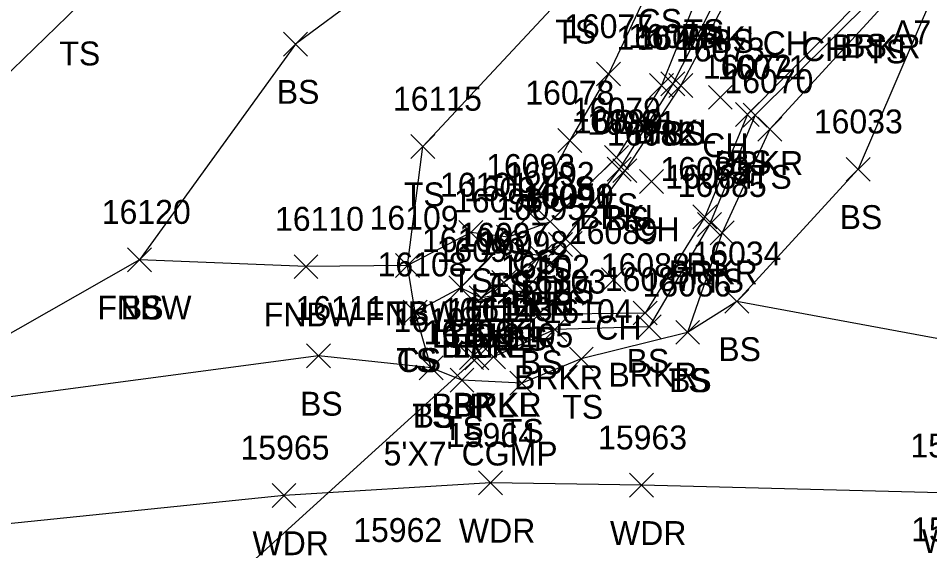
# Model space of a CAD drawing. Extents: x 1606530 to 1613020, y 784959 to 789666.
# Drawn here: x 1609253.6 to 1609329.8, y 788467.6 to 788511.7 of the extents above; entities that cross this region are included whole.
import ezdxf

# ---------------------------------------------------------------- set-up
doc = ezdxf.new("R2010")
doc.units = 0
for name, color, linetype in [('D_A', 7, 'Continuous'), ('D_C', 7, 'Continuous'), ('D_I', 7, 'Continuous'), ('D_TIC', 7, 'Continuous'), ('DCP', 7, 'Continuous'), ('L_A', 7, 'Continuous'), ('L_C', 7, 'Continuous'), ('L_I', 7, 'Continuous'), ('L_TIC', 7, 'Continuous'), ('LARO', 7, 'Continuous'), ('LAWA', 7, 'Continuous'), ('LAWE', 7, 'Continuous'), ('LELB', 7, 'Continuous'), ('LFNC', 7, 'Continuous')]:
    doc.layers.add(name, color=color, linetype=linetype)

msp = doc.modelspace()

# ---------------------------------------------------------------- linework, layer by layer
at = {"layer": 'D_TIC'}
for points in [[(1609290.934, 788482.273), (1609292.934, 788484.273)], [(1609292.934, 788482.273), (1609290.934, 788484.273)]]:
    msp.add_lwpolyline(points, dxfattribs=at)
at = {"layer": 'DCP'}
msp.add_lwpolyline([(1609180.836, 788382.354), (1609291.934, 788483.273)], dxfattribs=at)
at = {"layer": 'L_TIC'}
for points in [[(1609275.762, 788508.528), (1609277.762, 788510.528)], [(1609277.762, 788508.528), (1609275.762, 788510.528)], [(1609301.939, 788506.019), (1609303.939, 788508.019)], [(1609303.939, 788506.019), (1609301.939, 788508.019)], [(1609306.366, 788505.057), (1609308.366, 788507.057)], [(1609308.366, 788505.057), (1609306.366, 788507.057)], [(1609307.3, 788505.198), (1609309.3, 788507.198)], [(1609309.3, 788505.198), (1609307.3, 788507.198)], [(1609307.988, 788505.06), (1609309.988, 788507.06)], [(1609309.988, 788505.06), (1609307.988, 788507.06)], [(1609311.28, 788504.067), (1609313.28, 788506.067)], [(1609313.28, 788504.067), (1609311.28, 788506.067)], [(1609313.539, 788502.632), (1609315.539, 788504.632)], [(1609315.539, 788502.632), (1609313.539, 788504.632)], [(1609314.185, 788502.575), (1609316.185, 788504.575)], [(1609316.185, 788502.575), (1609314.185, 788504.575)], [(1609315.424, 788501.417), (1609317.424, 788503.417)], [(1609317.424, 788501.417), (1609315.424, 788503.417)], [(1609298.697, 788500.458), (1609300.697, 788502.458)], [(1609300.697, 788500.458), (1609298.697, 788502.458)], [(1609286.418, 788499.952), (1609288.418, 788501.952)], [(1609288.418, 788499.952), (1609286.418, 788501.952)], [(1609302.599, 788499.047), (1609304.599, 788501.047)], [(1609304.599, 788499.047), (1609302.599, 788501.047)], [(1609302.822, 788498.065), (1609304.822, 788500.065)], [(1609304.822, 788498.065), (1609302.822, 788500.065)], [(1609322.809, 788498.051), (1609324.809, 788500.051)], [(1609324.809, 788498.051), (1609322.809, 788500.051)], [(1609303.305, 788497.934), (1609305.305, 788499.934)], [(1609305.305, 788497.934), (1609303.305, 788499.934)], [(1609305.525, 788497.031), (1609307.525, 788499.031)], [(1609307.525, 788497.031), (1609305.525, 788499.031)], [(1609295.421, 788494.325), (1609297.421, 788496.325)], [(1609297.421, 788494.325), (1609295.421, 788496.325)], [(1609297.055, 788493.668), (1609299.055, 788495.668)], [(1609299.055, 788493.668), (1609297.055, 788495.668)], [(1609309.988, 788494.081), (1609311.988, 788496.081)], [(1609311.988, 788494.081), (1609309.988, 788496.081)], [(1609310.383, 788493.432), (1609312.383, 788495.432)], [(1609312.383, 788493.432), (1609310.383, 788495.432)], [(1609290.426, 788492.764), (1609292.426, 788494.764)], [(1609292.426, 788492.764), (1609290.426, 788494.764)], [(1609311.433, 788492.737), (1609313.433, 788494.737)], [(1609313.433, 788492.737), (1609311.433, 788494.737)], [(1609293.558, 788492.383), (1609295.558, 788494.383)], [(1609295.558, 788492.383), (1609293.558, 788494.383)], [(1609293.558, 788492.383), (1609295.558, 788494.383)], [(1609295.558, 788492.383), (1609293.558, 788494.383)], [(1609292.789, 788491.438), (1609294.789, 788493.438)], [(1609294.789, 788491.438), (1609292.789, 788493.438)], [(1609297.927, 788491.769), (1609299.927, 788493.769)], [(1609299.927, 788491.769), (1609297.927, 788493.769)], [(1609298.732, 788491.837), (1609300.732, 788493.837)], [(1609300.732, 788491.837), (1609298.732, 788493.837)], [(1609262.732, 788490.487), (1609264.732, 788492.487)], [(1609264.732, 788490.487), (1609262.732, 788492.487)], [(1609262.732, 788490.487), (1609264.732, 788492.487)], [(1609264.732, 788490.487), (1609262.732, 788492.487)], [(1609296.256, 788490.801), (1609298.256, 788492.801)], [(1609298.256, 788490.801), (1609296.256, 788492.801)], [(1609296.256, 788490.801), (1609298.256, 788492.801)], [(1609298.256, 788490.801), (1609296.256, 788492.801)], [(1609296.256, 788490.801), (1609298.256, 788492.801)], [(1609298.256, 788490.801), (1609296.256, 788492.801)], [(1609276.648, 788489.908), (1609278.648, 788491.908)], [(1609278.648, 788489.908), (1609276.648, 788491.908)], [(1609285.122, 788489.996), (1609287.122, 788491.996)], [(1609287.122, 788489.996), (1609285.122, 788491.996)], [(1609285.122, 788489.996), (1609287.122, 788491.996)], [(1609287.122, 788489.996), (1609285.122, 788491.996)], [(1609285.122, 788489.996), (1609287.122, 788491.996)], [(1609287.122, 788489.996), (1609285.122, 788491.996)], [(1609289.574, 788488.139), (1609291.574, 788490.139)], [(1609291.574, 788488.139), (1609289.574, 788490.139)], [(1609289.574, 788488.139), (1609291.574, 788490.139)], [(1609291.574, 788488.139), (1609289.574, 788490.139)], [(1609289.574, 788488.139), (1609291.574, 788490.139)], [(1609291.574, 788488.139), (1609289.574, 788490.139)], [(1609293.184, 788488.575), (1609295.184, 788490.575)], [(1609295.184, 788488.575), (1609293.184, 788490.575)], [(1609302.346, 788488.799), (1609304.346, 788490.799)], [(1609304.346, 788488.799), (1609302.346, 788490.799)], [(1609291.29, 788487.306), (1609293.29, 788489.306)], [(1609293.29, 788487.306), (1609291.29, 788489.306)], [(1609291.29, 788487.306), (1609293.29, 788489.306)], [(1609293.29, 788487.306), (1609291.29, 788489.306)], [(1609294.833, 788487.887), (1609296.833, 788489.887)], [(1609296.833, 788487.887), (1609294.833, 788489.887)], [(1609294.833, 788487.887), (1609296.833, 788489.887)], [(1609296.833, 788487.887), (1609294.833, 788489.887)], [(1609312.667, 788487.005), (1609314.667, 788489.005)], [(1609314.667, 788487.005), (1609312.667, 788489.005)], [(1609312.667, 788487.005), (1609314.667, 788489.005)], [(1609314.667, 788487.005), (1609312.667, 788489.005)], [(1609285.783, 788486.092), (1609287.783, 788488.092)], [(1609287.783, 788486.092), (1609285.783, 788488.092)], [(1609285.783, 788486.092), (1609287.783, 788488.092)], [(1609287.783, 788486.092), (1609285.783, 788488.092)], [(1609296.097, 788485.905), (1609298.097, 788487.905)], [(1609298.097, 788485.905), (1609296.097, 788487.905)], [(1609296.097, 788485.905), (1609298.097, 788487.905)], [(1609298.097, 788485.905), (1609296.097, 788487.905)], [(1609305.001, 788486.028), (1609307.001, 788488.028)], [(1609307.001, 788486.028), (1609305.001, 788488.028)], [(1609297.451, 788484.655), (1609299.451, 788486.655)], [(1609299.451, 788484.655), (1609297.451, 788486.655)], [(1609305.343, 788484.871), (1609307.343, 788486.871)], [(1609307.343, 788484.871), (1609305.343, 788486.871)], [(1609308.548, 788484.41), (1609310.548, 788486.41)], [(1609310.548, 788484.41), (1609308.548, 788486.41)], [(1609308.548, 788484.41), (1609310.548, 788486.41)], [(1609310.548, 788484.41), (1609308.548, 788486.41)], [(1609277.703, 788482.443), (1609279.703, 788484.443)], [(1609279.703, 788482.443), (1609277.703, 788484.443)], [(1609290.476, 788482.291), (1609292.476, 788484.291)], [(1609292.476, 788482.291), (1609290.476, 788484.291)], [(1609292.319, 788482.357), (1609294.319, 788484.357)], [(1609294.319, 788482.357), (1609292.319, 788484.357)], [(1609292.319, 788482.357), (1609294.319, 788484.357)], [(1609294.319, 788482.357), (1609292.319, 788484.357)], [(1609299.66, 788482.185), (1609301.66, 788484.185)], [(1609301.66, 788482.185), (1609299.66, 788484.185)], [(1609287.118, 788481.434), (1609289.118, 788483.434)], [(1609289.118, 788481.434), (1609287.118, 788483.434)], [(1609287.118, 788481.434), (1609289.118, 788483.434)], [(1609289.118, 788481.434), (1609287.118, 788483.434)], [(1609289.687, 788480.419), (1609291.687, 788482.419)], [(1609291.687, 788480.419), (1609289.687, 788482.419)], [(1609294.698, 788480.162), (1609296.698, 788482.162)], [(1609296.698, 788480.162), (1609294.698, 788482.162)], [(1609292.066, 788471.821), (1609294.066, 788473.821)], [(1609294.066, 788471.821), (1609292.066, 788473.821)], [(1609304.698, 788471.619), (1609306.698, 788473.619)], [(1609306.698, 788471.619), (1609304.698, 788473.619)], [(1609274.811, 788470.772), (1609276.811, 788472.772)], [(1609276.811, 788470.772), (1609274.811, 788472.772)]]:
    msp.add_lwpolyline(points, dxfattribs=at)
at = {"layer": 'LARO'}
for points in [[(1609297.256, 788491.801), (1609293.789, 788492.438), (1609290.574, 788489.139)], [(1609297.256, 788491.801), (1609295.833, 788488.887), (1609292.29, 788488.306), (1609290.574, 788489.139)]]:
    msp.add_lwpolyline(points, dxfattribs=at)
at = {"layer": 'LAWA'}
msp.add_lwpolyline([(1609458.893, 788516.216), (1609465.518, 788489.735), (1609475.82, 788469.822), (1609458.93, 788473.776), (1609440.54, 788476.414), (1609422.319, 788472.182), (1609400.858, 788472.527), (1609378.742, 788469.077), (1609331.758, 788471.946), (1609305.698, 788472.619), (1609293.066, 788472.821), (1609275.811, 788471.772), (1609233.209, 788467.381), (1609185.699, 788461.65), (1609159.09, 788461.178), (1609160.3, 788482.227), (1609154.118, 788496.013), (1609177.082, 788505.785)], dxfattribs=at)
at = {"layer": 'LAWE'}
for points in [[(1609338.265, 788592.862), (1609325.525, 788576.58), (1609316.807, 788561.044), (1609315.365, 788553.22), (1609314.764, 788542.332), (1609313.606, 788524.981), (1609312.272, 788514.017), (1609308.3, 788506.198), (1609303.822, 788499.065), (1609298.927, 788492.769), (1609297.256, 788491.801), (1609294.184, 788489.575), (1609292.29, 788488.306), (1609291.476, 788483.291), (1609293.319, 788483.357)], [(1609344.132, 788584.453), (1609332.99, 788571.865), (1609323.348, 788550.774), (1609321.859, 788539.543), (1609326.22, 788524.89), (1609324.997, 788513.339), (1609315.185, 788503.575), (1609311.383, 788494.432), (1609306.343, 788485.871), (1609298.451, 788485.655), (1609293.319, 788483.357)]]:
    msp.add_lwpolyline(points, dxfattribs=at)
at = {"layer": 'LELB'}
for points in [[(1609345.504, 788583.398), (1609333.653, 788571.33), (1609324.885, 788550.763), (1609323.314, 788539.546), (1609327.591, 788524.41), (1609326.059, 788512.915), (1609316.424, 788502.417), (1609312.433, 788493.737), (1609309.548, 788485.41), (1609300.66, 788483.185), (1609295.698, 788481.162), (1609290.687, 788481.419), (1609288.118, 788482.434), (1609286.783, 788487.092), (1609286.122, 788490.996), (1609287.418, 788500.952), (1609300.084, 788514.569), (1609305.812, 788532.988), (1609305.239, 788558.079), (1609320.597, 788588.369), (1609325.511, 788599.313)], [(1609344.018, 788584.804), (1609331.2, 788572.095), (1609322.01, 788550.979), (1609321.14, 788539.885), (1609325.729, 788524.414), (1609324.195, 788513.38), (1609314.539, 788503.632), (1609310.988, 788495.081), (1609306.001, 788487.028), (1609297.097, 788486.905)], [(1609366.827, 788579.614), (1609348.341, 788574.614), (1609345.128, 788559.502), (1609339.409, 788545.413), (1609353.526, 788532.076), (1609355.901, 788515.928), (1609350.146, 788501.166), (1609342.753, 788489.296), (1609336.962, 788484.436), (1609343.274, 788499.194), (1609340.298, 788515.898), (1609331.632, 788517.324), (1609323.809, 788499.051), (1609313.667, 788488.005), (1609309.548, 788485.41)], [(1609305.239, 788558.079), (1609292.123, 788546.533), (1609272.297, 788525.77), (1609258.625, 788512.741), (1609243.895, 788498.471), (1609227.282, 788490.211), (1609208.034, 788485.11), (1609185.28, 788481.504)], [(1609313.343, 788542.776), (1609313.191, 788524.895), (1609310.792, 788514.607), (1609307.366, 788506.057), (1609303.599, 788500.047), (1609298.055, 788494.668), (1609294.558, 788493.383), (1609291.426, 788493.764), (1609286.122, 788490.996)], [(1609313.343, 788542.776), (1609309.302, 788525.609), (1609306.922, 788515.462), (1609302.939, 788507.019), (1609299.697, 788501.458), (1609296.421, 788495.325), (1609294.558, 788493.383), (1609290.574, 788489.139), (1609286.783, 788487.092)], [(1609315.721, 788542.334), (1609314.405, 788525.163), (1609313.075, 788513.791), (1609308.988, 788506.06), (1609304.305, 788498.934), (1609299.732, 788492.837), (1609295.833, 788488.887), (1609297.097, 788486.905)], [(1609426.503, 788537.087), (1609427.324, 788507.853), (1609421.658, 788499.174), (1609408.568, 788488.921), (1609374.203, 788482.146), (1609350.434, 788482.457), (1609336.962, 788484.436), (1609333.393, 788484.335), (1609313.667, 788488.005)], [(1609305.812, 788532.988), (1609293.728, 788522.094), (1609276.762, 788509.528), (1609263.732, 788491.487), (1609240.783, 788478.4)], [(1609288.118, 788482.434), (1609278.703, 788483.443), (1609240.783, 788478.4), (1609207.147, 788476.739), (1609190.021, 788470.466), (1609159.09, 788461.178)]]:
    msp.add_lwpolyline(points, dxfattribs=at)
at = {"layer": 'LFNC'}
msp.add_lwpolyline([(1609286.122, 788490.996), (1609277.648, 788490.908), (1609263.732, 788491.487)], dxfattribs=at)

# ---------------------------------------------------------------- texts
at = {"layer": 'D_A'}
msp.add_text('P', height=2, dxfattribs=at).set_placement((1609291.312, 788478.273))
at = {"layer": 'D_C'}
msp.add_text("5'X7' CGMP", height=2, dxfattribs=at).set_placement((1609284.131, 788474.273))
at = {"layer": 'D_I'}
msp.add_text('16114', height=2, dxfattribs=at).set_placement((1609289.43, 788486.273))
at = {"layer": 'L_A'}
for s, p in [('CS', (1609305.363, 788510.462)), ('TS', (1609298.493, 788509.569)), ('TS', (1609309.202, 788509.607)), ('BRKL', (1609308.918, 788509.017)), ('BS', (1609311.516, 788508.791)), ('CH', (1609315.826, 788508.59)), ('CH', (1609319.106, 788508.098)), ('BRKR', (1609321.588, 788508.339)), ('BS', (1609322.636, 788508.38)), ('TS', (1609324.468, 788507.915)), ('TS', (1609257.035, 788507.741)), ('BS', (1609275.203, 788504.528)), ('CS', (1609301.38, 788502.019)), ('BRKL', (1609304.945, 788501.198)), ('TS', (1609305.775, 788501.057)), ('BS', (1609307.429, 788501.06)), ('CH', (1609310.768, 788500.067)), ('BRKR', (1609311.776, 788498.575)), ('BS', (1609312.98, 788498.632)), ('TS', (1609314.834, 788497.417)), ('CS', (1609298.138, 788496.458)), ('TS', (1609285.827, 788495.952)), ('TS', (1609302.008, 788495.047)), ('BRKL', (1609300.468, 788494.065)), ('BS', (1609302.746, 788493.934)), ('BS', (1609322.25, 788494.051)), ('CH', (1609305.013, 788493.031)), ('CS', (1609294.862, 788490.325)), ('TS', (1609296.465, 788489.668)), ('BS', (1609309.429, 788490.081)), ('BRKR', (1609307.974, 788489.432)), ('TS', (1609289.835, 788488.764)), ('TS', (1609292.968, 788488.383)), ('CS', (1609292.999, 788488.383)), ('TS', (1609310.843, 788488.737)), ('LEL', (1609291.427, 788487.438)), ('BRKL', (1609295.572, 788487.769)), ('BS', (1609298.173, 788487.837)), ('BRKL', (1609293.902, 788486.801)), ('LER', (1609294.839, 788486.801)), ('LEL', (1609294.894, 788486.801)), ('FNBW', (1609260.204, 788486.487)), ('BS', (1609262.173, 788486.487)), ('FNBW', (1609274.12, 788485.908)), ('FNBW', (1609282.595, 788485.996)), ('TS', (1609284.532, 788485.996)), ('TS', (1609284.532, 788485.996)), ('BRKL', (1609290.83, 788484.575)), ('CH', (1609301.834, 788484.799)), ('LER', (1609288.157, 788484.139)), ('LEL', (1609288.212, 788484.139)), ('CS', (1609289.015, 788484.139)), ('LER', (1609293.416, 788483.887)), ('BS', (1609294.274, 788483.887)), ('BRKL', (1609288.935, 788483.306)), ('LER', (1609289.872, 788483.306)), ('BS', (1609312.108, 788483.005)), ('BS', (1609312.108, 788483.005)), ('TS', (1609285.193, 788482.092)), ('CS', (1609285.224, 788482.092)), ('BS', (1609304.442, 788482.028)), ('BS', (1609295.538, 788481.905)), ('BS', (1609295.538, 788481.905)), ('BRKR', (1609295.041, 788480.655)), ('BRKR', (1609302.934, 788480.871)), ('TS', (1609307.957, 788480.41)), ('BS', (1609307.989, 788480.41)), ('BS', (1609277.144, 788478.443)), ('BRKL', (1609288.122, 788478.291)), ('BRKR', (1609289.91, 788478.357)), ('BRKL', (1609289.965, 788478.357)), ('TS', (1609299.07, 788478.185)), ('TS', (1609286.528, 788477.434)), ('BS', (1609286.559, 788477.434)), ('TS', (1609289.096, 788476.419)), ('TS', (1609294.107, 788476.162)), ('WDR', (1609290.429, 788467.821)), ('WDR', (1609303.06, 788467.619)), ('WDR', (1609273.173, 788466.772)), ('WDR', (1609329.12, 788466.946))]:
    msp.add_text(s, height=2, dxfattribs=at).set_placement(p)
at = {"layer": 'L_C'}
msp.add_text('A7', height=2, dxfattribs=at).set_placement((1609326.644, 788509.51))
at = {"layer": 'L_I'}
for s, p in [('16077', (1609299.223, 788510.019)), ('16076', (1609303.594, 788509.057)), ('16075', (1609304.583, 788509.198)), ('16074', (1609305.271, 788509.06)), ('16073', (1609308.563, 788508.067)), ('16072', (1609310.822, 788506.632)), ('16071', (1609312.036, 788506.575)), ('16070', (1609312.621, 788505.417)), ('16078', (1609295.98, 788504.458)), ('16115', (1609284.914, 788503.952)), ('16079', (1609299.875, 788503.047)), ('16080', (1609300.019, 788502.065)), ('16081', (1609301.156, 788501.934)), ('16033', (1609320.092, 788502.051)), ('16082', (1609302.809, 788501.031)), ('16093', (1609292.705, 788498.325)), ('16083', (1609307.271, 788498.081)), ('16092', (1609294.339, 788497.668)), ('16084', (1609307.667, 788497.432)), ('16101', (1609288.843, 788496.764)), ('16085', (1609308.717, 788496.737)), ('16094', (1609290.842, 788496.383)), ('16094', (1609290.842, 788496.383)), ('16091', (1609295.777, 788495.769)), ('16090', (1609295.929, 788495.837)), ('16096', (1609290.018, 788495.438)), ('16120', (1609260.575, 788494.487)), ('16120', (1609260.575, 788494.487)), ('16095', (1609293.54, 788494.801)), ('16095', (1609293.54, 788494.801)), ('16095', (1609293.54, 788494.801)), ('16110', (1609275.058, 788493.908)), ('16109', (1609282.965, 788493.996)), ('16109', (1609282.965, 788493.996)), ('16109', (1609282.965, 788493.996)), ('16089', (1609299.621, 788492.799)), ('16100', (1609287.338, 788492.139)), ('16100', (1609287.338, 788492.139)), ('16100', (1609287.338, 788492.139)), ('16097', (1609290.468, 788492.575)), ('16098', (1609292.117, 788491.887)), ('16098', (1609292.117, 788491.887)), ('16099', (1609288.565, 788491.306)), ('16099', (1609288.565, 788491.306)), ('16034', (1609309.951, 788491.005)), ('16034', (1609309.951, 788491.005)), ('16108', (1609283.634, 788490.092)), ('16108', (1609283.634, 788490.092)), ('16102', (1609293.948, 788489.905)), ('16102', (1609293.948, 788489.905)), ('16088', (1609302.285, 788490.028)), ('16087', (1609302.627, 788488.871)), ('16103', (1609295.301, 788488.655)), ('16086', (1609305.776, 788488.41)), ('16086', (1609305.776, 788488.41)), ('16111', (1609276.767, 788486.443)), ('16112', (1609288.973, 788486.291)), ('16113', (1609290.816, 788486.357)), ('16113', (1609290.816, 788486.357)), ('16104', (1609297.511, 788486.185)), ('16107', (1609284.969, 788485.434)), ('16107', (1609284.969, 788485.434)), ('16106', (1609287.483, 788484.419)), ('16105', (1609292.548, 788484.162)), ('15964', (1609289.429, 788475.821)), ('15963', (1609302.06, 788475.619)), ('15965', (1609272.173, 788474.772)), ('15954', (1609328.168, 788474.946)), ('15962', (1609281.595, 788467.875)), ('15955', (1609328.229, 788467.93))]:
    msp.add_text(s, height=2, dxfattribs=at).set_placement(p)

doc.saveas('drawing.dxf')
